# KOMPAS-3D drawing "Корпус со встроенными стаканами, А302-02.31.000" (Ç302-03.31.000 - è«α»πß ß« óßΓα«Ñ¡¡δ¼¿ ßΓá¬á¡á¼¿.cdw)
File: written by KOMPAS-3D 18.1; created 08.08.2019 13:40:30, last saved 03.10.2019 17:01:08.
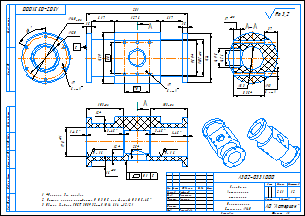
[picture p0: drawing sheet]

Sheet 1: A3, landscape

Document properties: Автор: Пользователь Windows; Полное имя файла: D:\Мембранные насосы\Мембранный электропривод\А302-00.00.000 - ASTRA-302 (МЭ200)\Чертежи Полипропилен\А302-03.31.000 - Корпус со встроенными стаканами.cdw; Параметр неуказанной шероховатости: Ra 3,2; Масса: 2.60942

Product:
- Part/product: Корпус со встроенными стаканами  | designation А302-02.31.000  | pos. 2
    Материал: Поливинилхлорид (density 1350 kg/m3)
    Масса: 3.18846
    source file: ..\3Д ПВХ\А302-02.00.000 - ASTRA-302 (МЭ200)\А302-02.31.000 - Корпус со встроенными стаканами.cdw, ..\Чертежи ПВХ\А302-02.31.000 - Корпус со встроенными стаканами.cdw
  - Body: Тело 18
      Масса: 3.54993
  - Body: Тело 19
      Масса: 3.54993
  - Body: (unnamed)
      Масса: 3.54993
- Part/product: Корпус со встроенными стаканами  | designation А302-01.31.000
    Материал: Поливинилхлорид (density 1350 kg/m3)
    Масса: 2.63451
- Part/product: Корпус со встроенными стаканами  | designation А302-03.31.000  | pos. 2
    Материал: Поливинилхлорид (density 1350 kg/m3)
    Масса: 2.60942
    source file: ..\..\А302-03.00.000 - ASTRA-302 (МЭ200)\А302-03.31.000 - Корпус со встроенными стаканами.cdw, А302-03.31.000 - Корпус со встроенными стаканами.cdw
  - Body: (unnamed)
      Масса: 3.54993
  - Body: Тело 18
      Масса: 3.54993
  - Body: Тело 19
      Масса: 3.54993

Title block, sheet 1: Наименование: Корпус со / встроенными / стаканами; designation: А302-03.31.000; Материал: Полипропилен / Стержень  140; Масса: 2,61; Количество листов документа: 1; organisation: АО "Астерион"; Форматы листов документа: A3; stored path: D:\Мембранные насосы\Мембранный электропривод\А302-00.00.000 - ASTRA-302 (МЭ200)\3Д ПВХ\А302-02.00.000 - ASTRA-302 (МЭ200)\А302-02.31.000 - Корпус со встроенными стаканами.cdw; Разработал: Лифлянд; Проверил: Борисенко; Т. контр.: Лучихин; Утвердил: Григорбева

Views: Проекционный вид 2, Слева, Проекционный вид 3, Разрез А-А, Проекционный вид 8, Местный разрез 1, Проекционный вид 12
Referenced files in D:\Мембранные насосы\Мембранный электропривод\А302-00.00.000 - ASTRA-302 (МЭ200)\3Д ПВХ\: А302-01.31.000 - Корпус со встроенными стаканами.m3d
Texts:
  Ra 1,6
  Ra 3,2
Dimensions and other numbers on the sheet: 140; 120; 7; 6 отв.; 281; 134; 102; 15; 61,7; 127,6; 95,9; 70; 88; 139; 49,5; 63; 17; 37; 83,5; 42,6; 13; 103; 1; 3; 78; 16; 2,5; 12; 0,1; 1:2; 2,61

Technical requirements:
  *Размеры для справок.
  Острые кромки притупить R 0,3...0,5 или фаской 0,3...0,5х45 .
  Общие допуски ГОСТ 30893.2-mK (H14, h14,  t2/2).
